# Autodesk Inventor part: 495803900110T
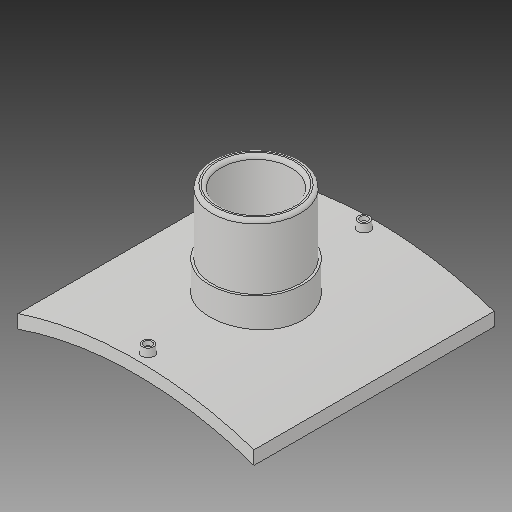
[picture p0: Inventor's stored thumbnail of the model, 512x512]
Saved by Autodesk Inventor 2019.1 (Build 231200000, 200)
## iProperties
Created: 2017-10
Part Number: 495803900110T
Material: Generic
Description: PLASSON BRANCH SADDLE  900x110
Document SubType Name: Modeling
Designer: KIM
Mass: 2754.05 g
Surface Area: 3037.44 cm^2
Volume: 2754.05 cm^3
Density: 1 g/cm^3
Appearance: Default
Author: KIM
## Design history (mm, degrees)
derived "495803.ipt"
feature "Solid1::495803.ipt"
tag "TaggingFeature1"
body "Solid1"
other parameters: "d1" = 16, "d2" = 295, "d4" = 0, "d12" = 475.6, "d13" = 14, "d14" = 135, "d16" = 5 deg, "d18" = 4, "d19" = 14, "d20" = 0, "d21" = 3, "d22" = 0, "d23" = 581, "d24" = 115.5, "d25" = 16, "d26" = 88, "d28" = 0, "d29" = 9.6, "d31" = 0, "d32" = 57.5, "d33" = 0, "d34" = 9, "d37" = 80.5, "d38" = 0, "d39" = 4.5, "B_" = 295, "H_" = 115, "x_" = 16, "D_" = 16
